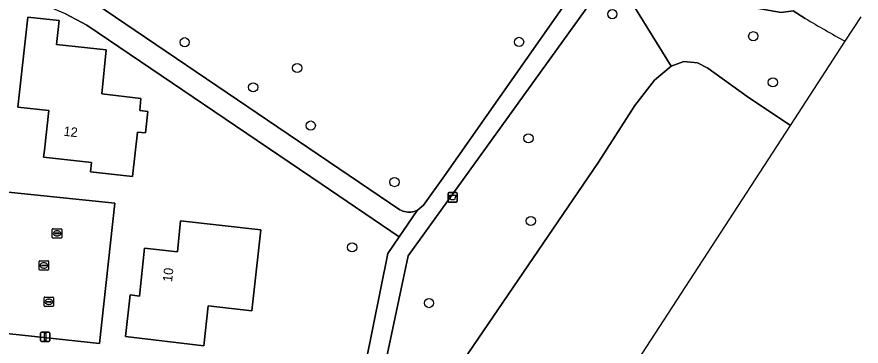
# Model space of a CAD drawing. Extents: x 161928 to 163071, y 386474 to 387428.
# Drawn here: x 162422.4 to 162512.1, y 386616.9 to 386651.9 of the extents above; entities that cross this region are included whole.
import ezdxf

# ---------------------------------------------------------------- set-up
doc = ezdxf.new("R2010")
doc.units = 0
for name, color, linetype in [('IMGEO_Afvalbak', 7, 'Continuous'), ('IMGEO_Boom', 7, 'Continuous'), ('IMGEO_Erf', 7, 'Continuous'), ('IMGEO_Groenvoorziening', 7, 'Continuous'), ('IMGEO_Kolk', 7, 'Continuous'), ('IMGEO_Lichtmast', 7, 'Continuous'), ('IMGEO_Meer_plas_ven_vijver', 7, 'Continuous'), ('IMGEO_Pand', 7, 'Continuous'), ('IMGEO_Pand_nummerreeks', 7, 'Continuous'), ('IMGEO_Rijbaan_lokaal_open', 7, 'Continuous'), ('IMGEO_Rioolput', 7, 'Continuous'), ('IMGEO_Voetpad_halfverhard', 7, 'Continuous'), ('IMGEO_Voetpad_open', 7, 'Continuous')]:
    doc.layers.add(name, color=color, linetype=linetype)

msp = doc.modelspace()

# ---------------------------------------------------------------- linework, layer by layer
at = {"layer": 'IMGEO_Afvalbak'}
for p, q in [((162468.22, 386632.306), (162468.22, 386633.106)), ((162468.22, 386633.106), (162468.22, 386632.306)), ((162468.32, 386633.206), (162469.11, 386633.206)), ((162469.11, 386633.206), (162468.32, 386633.206)), ((162469.21, 386633.106), (162469.21, 386632.306)), ((162469.21, 386632.306), (162469.21, 386633.106)), ((162469.11, 386632.206), (162468.32, 386632.206)), ((162468.32, 386632.206), (162469.11, 386632.206))]:
    msp.add_line(p, q, dxfattribs=at)
msp.add_lwpolyline([(162468.363, 386632.92), (162469.067, 386632.92), (162468.918, 386632.45), (162468.512, 386632.45), (162468.363, 386632.92)], dxfattribs=at)
for centre, start, end in [((162468.32, 386633.106), 90, 180), ((162468.32, 386633.106), 90, 180), ((162469.11, 386633.106), 0, 90), ((162469.11, 386633.106), 360, 90), ((162468.32, 386632.306), 180, 270), ((162468.32, 386632.306), 180, 270), ((162469.11, 386632.306), 270, 0), ((162469.11, 386632.306), 270, 0)]:
    msp.add_arc(centre, 0.1, start, end, dxfattribs=at)
at = {"layer": 'IMGEO_Boom'}
for centre in [(162485.683, 386652.188), (162500.662, 386649.842), (162440.231, 386649.202), (162475.774, 386649.237), (162452.191, 386646.458), (162447.512, 386644.407), (162502.751, 386644.934), (162453.631, 386640.337), (162476.768, 386638.978), (162462.536, 386634.326), (162477.027, 386630.191), (162458.028, 386627.386), (162466.196, 386621.456)]:
    msp.add_circle(centre, 0.489, dxfattribs=at)
at = {"layer": 'IMGEO_Erf'}
for points in [[(162454.731, 386634.129), (162429.842, 386651.007), (162427.559, 386652.217), (162425.176, 386653.219), (162422.714, 386654.003), (162420.192, 386654.565), (162418.483, 386654.813), (162405.257, 386656.292), (162404.515, 386649.308), (162403.939, 386643.891), (162402.493, 386630.278), (162416.503, 386628.855)], [(162415.579, 386623.904), (162401.954, 386625.399), (162400.548, 386612.657), (162395.336, 386564.99), (162414.895, 386562.738), (162421.638, 386561.962), (162444.564, 386594.917), (162445.356, 386594.4), (162447.893, 386598.102), (162459.435, 386614.943), (162461.829, 386626.715), (162463.03, 386628.501), (162454.731, 386634.129)], [(162420.711, 386632.302), (162420.785, 386633.326), (162432.793, 386632.1), (162431.191, 386617.163), (162419.313, 386618.428), (162419.342, 386619.587)]]:
    msp.add_lwpolyline(points, dxfattribs=at)
for points in [[(162422.482, 386642.308), (162423.277, 386649.318), (162423.568, 386651.883), (162426.903, 386651.52), (162426.624, 386648.954), (162431.897, 386648.381), (162431.422, 386643.704), (162435.586, 386643.231), (162435.464, 386641.939), (162436.32, 386641.836), (162436.084, 386639.557), (162435.227, 386639.637), (162434.673, 386634.909), (162430.22, 386635.411), (162430.319, 386636.393), (162425.232, 386636.966), (162425.319, 386637.74), (162425.792, 386641.935)], [(162439.453, 386626.908), (162439.792, 386630.221), (162448.336, 386629.248), (162447.381, 386620.627), (162442.745, 386621.147), (162442.266, 386616.916), (162433.928, 386617.89), (162434.425, 386622.336), (162435.429, 386622.204), (162435.974, 386627.293)]]:
    msp.add_lwpolyline(points, close=True, dxfattribs=at)
at = {"layer": 'IMGEO_Groenvoorziening'}
for points in [[(162430.677, 386653.35), (162463.112, 386631.382), (162463.267, 386631.302), (162463.428, 386631.236), (162463.595, 386631.185), (162463.765, 386631.15), (162463.938, 386631.129), (162464.112, 386631.124), (162464.286, 386631.134), (162464.458, 386631.16), (162464.627, 386631.202), (162464.792, 386631.258), (162464.925, 386631.316), (162465.604, 386631.858), (162467.845, 386635.008), (162488.421, 386664.371)], [(162422.397, 386543.77), (162427.166, 386551.666), (162433.134, 386560.84), (162440.537, 386571.577), (162443.391, 386575.338), (162463.65, 386605.442), (162468.197, 386612.928), (162484.213, 386636.459), (162488.061, 386642.46), (162490.173, 386645.183), (162491.955, 386646.67), (162486.524, 386655.466), (162484.527, 386655.077), (162463.996, 386626.469), (162461.367, 386614.091), (162441.634, 386585.218), (162440.702, 386585.864), (162418.182, 386553.338)], [(162506.186, 386651.728), (162504.888, 386652.554), (162503.64, 386652.359), (162500, 386653.02), (162486.524, 386655.466), (162491.955, 386646.67), (162493.287, 386647.171), (162494.722, 386647.011), (162495.834, 386646.435), (162500, 386643.42), (162504.627, 386640.362), (162510.432, 386649.303)]]:
    msp.add_lwpolyline(points, dxfattribs=at)
msp.add_arc((162647.941, 386895.038), 281.592, 239.77456, 240.76941, dxfattribs=at)
at = {"layer": 'IMGEO_Kolk'}
for p, q in [((162426.164, 386628.446), (162426.164, 386629.298)), ((162426.239, 386629.372), (162427.091, 386629.372)), ((162426.423, 386628.866), (162426.423, 386628.878)), ((162426.861, 386628.829), (162426.463, 386628.829)), ((162426.466, 386628.915), (162426.864, 386628.915)), ((162426.675, 386628.592), (162426.65, 386628.592)), ((162426.652, 386629.152), (162426.677, 386629.152)), ((162426.907, 386628.878), (162426.907, 386628.866)), ((162427.165, 386629.298), (162427.165, 386628.446)), ((162427.091, 386628.372), (162426.239, 386628.372)), ((162425.283, 386621.171), (162425.283, 386622.023)), ((162425.358, 386622.097), (162426.21, 386622.097)), ((162425.542, 386621.591), (162425.542, 386621.603)), ((162425.98, 386621.554), (162425.582, 386621.554)), ((162425.585, 386621.64), (162425.983, 386621.64)), ((162425.771, 386621.877), (162425.796, 386621.877)), ((162426.026, 386621.603), (162426.026, 386621.591)), ((162426.284, 386622.023), (162426.284, 386621.171)), ((162426.21, 386621.097), (162425.358, 386621.097)), ((162425.794, 386621.317), (162425.769, 386621.317))]:
    msp.add_line(p, q, dxfattribs=at)
for points in [[(162426.164, 386628.446), (162426.164, 386629.298)], [(162426.239, 386629.372), (162427.091, 386629.372)], [(162427.165, 386629.298), (162427.165, 386628.446)], [(162427.091, 386628.372), (162426.239, 386628.372)], [(162425.283, 386621.171), (162425.283, 386622.023)], [(162425.358, 386622.097), (162426.21, 386622.097)], [(162426.284, 386622.023), (162426.284, 386621.171)], [(162426.21, 386621.097), (162425.358, 386621.097)]]:
    msp.add_lwpolyline(points, dxfattribs=at)
for centre, radius, start, end in [((162426.241, 386629.296), 0.0765, 91.55205, 178.44795), ((162426.241, 386629.296), 0.0765, 91.55205, 178.44795), ((162426.463, 386628.875), 0.0403, 85.87752, 175.75265), ((162426.46, 386628.865), 0.0366, 178.93798, 274.71019), ((162426.864, 386628.872), 0.043, 264.86636, 352.45326), ((162426.868, 386628.877), 0.0386, 1.73085, 96.63898), ((162427.089, 386629.296), 0.0765, 1.55205, 88.44795), ((162427.089, 386629.296), 0.0765, 1.55205, 88.44795), ((162426.241, 386628.448), 0.0765, 181.55205, 268.44795), ((162426.241, 386628.448), 0.0765, 181.55205, 268.44795), ((162427.089, 386628.448), 0.0765, 271.55205, 358.44795), ((162427.089, 386628.448), 0.0765, 271.55205, 358.44795), ((162425.36, 386622.021), 0.0765, 91.55205, 178.44795), ((162425.36, 386622.021), 0.0765, 91.55205, 178.44795), ((162425.582, 386621.6), 0.0403, 85.87752, 175.75265), ((162425.579, 386621.59), 0.0366, 178.93798, 274.71019), ((162425.983, 386621.597), 0.043, 264.86636, 352.45326), ((162425.987, 386621.602), 0.0386, 1.73085, 96.63898), ((162426.208, 386622.021), 0.0765, 1.55205, 88.44795), ((162426.208, 386622.021), 0.0765, 1.55205, 88.44795), ((162425.36, 386621.173), 0.0765, 181.55205, 268.44795), ((162425.36, 386621.173), 0.0765, 181.55205, 268.44795), ((162426.208, 386621.173), 0.0765, 271.55205, 358.44795), ((162426.208, 386621.173), 0.0765, 271.55205, 358.44795)]:
    msp.add_arc(centre, radius, start, end, dxfattribs=at)
for centre, major_axis, ratio, start_param, end_param in [((162426.651, 386628.872), (-0.387, 0.002), 0.722429, 4.712389, 7.853982), ((162426.676, 386628.872), (-0.39, 0.002), 0.717154, 1.570796, 4.712389), ((162425.77, 386621.597), (-0.387, 0.002), 0.722429, 4.712389, 7.853982), ((162425.795, 386621.597), (-0.39, 0.002), 0.717154, 1.570796, 4.712389)]:
    msp.add_ellipse(centre, major_axis=major_axis, ratio=ratio, start_param=start_param, end_param=end_param, dxfattribs=at)
at = {"layer": 'IMGEO_Lichtmast'}
for p, q in [((162424.904, 386617.466), (162424.904, 386618.266)), ((162424.904, 386618.266), (162424.904, 386617.466)), ((162425.004, 386618.366), (162425.794, 386618.366)), ((162425.794, 386618.366), (162425.004, 386618.366)), ((162425.894, 386618.266), (162425.894, 386617.466)), ((162425.894, 386617.466), (162425.894, 386618.266)), ((162425.794, 386617.366), (162425.004, 386617.366)), ((162425.004, 386617.366), (162425.794, 386617.366))]:
    msp.add_line(p, q, dxfattribs=at)
msp.add_lwpolyline([(162425.324, 386618.241), (162425.474, 386618.241), (162425.474, 386617.491), (162425.324, 386617.491), (162425.324, 386618.241)], dxfattribs=at)
for centre, start, end in [((162425.004, 386618.266), 90, 180), ((162425.004, 386618.266), 90, 180), ((162425.794, 386618.266), 0, 90), ((162425.794, 386618.266), 360, 90), ((162425.004, 386617.466), 180, 270), ((162425.004, 386617.466), 180, 270), ((162425.794, 386617.466), 270, 0), ((162425.794, 386617.466), 270, 0)]:
    msp.add_arc(centre, 0.1, start, end, dxfattribs=at)
at = {"layer": 'IMGEO_Meer_plas_ven_vijver'}
msp.add_lwpolyline([(162413.433, 386500.536), (162486.069, 386611.772), (162504.627, 386640.362), (162500, 386643.42), (162495.834, 386646.435), (162494.722, 386647.011), (162493.287, 386647.171), (162491.955, 386646.67), (162490.173, 386645.183), (162488.061, 386642.46), (162484.213, 386636.459), (162468.197, 386612.928), (162463.65, 386605.442), (162443.391, 386575.338), (162440.537, 386571.577), (162433.134, 386560.84), (162427.166, 386551.666), (162422.397, 386543.77)], dxfattribs=at)
at = {"layer": 'IMGEO_Pand'}
for points in [[(162436.32, 386641.836), (162435.464, 386641.939), (162435.586, 386643.231), (162431.422, 386643.704), (162431.897, 386648.381), (162426.624, 386648.954), (162426.903, 386651.52), (162423.568, 386651.883), (162423.277, 386649.318), (162422.482, 386642.308), (162425.792, 386641.935), (162425.319, 386637.74), (162425.232, 386636.966), (162430.319, 386636.393), (162430.22, 386635.411), (162434.673, 386634.909), (162435.227, 386639.637), (162436.084, 386639.557)], [(162435.429, 386622.204), (162434.425, 386622.336), (162433.928, 386617.89), (162442.266, 386616.916), (162442.745, 386621.147), (162447.381, 386620.627), (162448.336, 386629.248), (162439.792, 386630.221), (162439.453, 386626.908), (162435.974, 386627.293)]]:
    msp.add_lwpolyline(points, close=True, dxfattribs=at)
at = {"layer": 'IMGEO_Rijbaan_lokaal_open'}
msp.add_lwpolyline([(162419.342, 386619.587), (162419.313, 386618.428), (162431.191, 386617.163), (162432.793, 386632.1), (162420.785, 386633.326), (162420.711, 386632.302)], dxfattribs=at)
at = {"layer": 'IMGEO_Rioolput'}
for p, q in [((162424.763, 386625.032), (162424.763, 386625.884)), ((162424.838, 386625.958), (162425.69, 386625.958)), ((162425.764, 386625.884), (162425.764, 386625.032)), ((162425.69, 386624.958), (162424.838, 386624.958)), ((162425.022, 386625.452), (162425.022, 386625.464)), ((162425.46, 386625.415), (162425.062, 386625.415)), ((162425.065, 386625.501), (162425.463, 386625.501)), ((162425.274, 386625.178), (162425.249, 386625.178)), ((162425.251, 386625.738), (162425.276, 386625.738)), ((162425.506, 386625.464), (162425.506, 386625.452))]:
    msp.add_line(p, q, dxfattribs=at)
for points in [[(162424.763, 386625.032), (162424.763, 386625.884)], [(162424.838, 386625.958), (162425.69, 386625.958)], [(162425.764, 386625.884), (162425.764, 386625.032)], [(162425.69, 386624.958), (162424.838, 386624.958)]]:
    msp.add_lwpolyline(points, dxfattribs=at)
for centre, radius, start, end in [((162424.84, 386625.882), 0.0765, 91.55205, 178.44795), ((162424.84, 386625.882), 0.0765, 91.55205, 178.44795), ((162425.688, 386625.882), 0.0765, 1.55205, 88.44795), ((162425.688, 386625.882), 0.0765, 1.55205, 88.44795), ((162424.84, 386625.034), 0.0765, 181.55205, 268.44795), ((162424.84, 386625.034), 0.0765, 181.55205, 268.44795), ((162425.062, 386625.461), 0.0403, 85.87752, 175.75265), ((162425.059, 386625.451), 0.0366, 178.93798, 274.71019), ((162425.463, 386625.458), 0.043, 264.86636, 352.45326), ((162425.467, 386625.463), 0.0386, 1.73085, 96.63898), ((162425.688, 386625.034), 0.0765, 271.55205, 358.44795), ((162425.688, 386625.034), 0.0765, 271.55205, 358.44795)]:
    msp.add_arc(centre, radius, start, end, dxfattribs=at)
for centre, major_axis, ratio, start_param, end_param in [((162425.25, 386625.458), (-0.387, 0.002), 0.722429, 4.712389, 7.853982), ((162425.275, 386625.458), (-0.39, 0.002), 0.717154, 1.570796, 4.712389)]:
    msp.add_ellipse(centre, major_axis=major_axis, ratio=ratio, start_param=start_param, end_param=end_param, dxfattribs=at)
at = {"layer": 'IMGEO_Voetpad_halfverhard'}
for points in [[(162499.594, 386656.083), (162499.263, 386656.313), (162499.135, 386656.201), (162498.803, 386656.095), (162497.85, 386655.862), (162487.291, 386658.568), (162490.455, 386662.814), (162488.421, 386664.371), (162467.845, 386635.008), (162465.604, 386631.858), (162464.925, 386631.316), (162463.03, 386628.501), (162461.829, 386626.715), (162459.435, 386614.943), (162447.893, 386598.102), (162445.356, 386594.4), (162444.564, 386594.917), (162421.638, 386561.962), (162417.322, 386555.758)], [(162463.996, 386626.469), (162484.527, 386655.077), (162486.524, 386655.466), (162500, 386653.02), (162503.64, 386652.359), (162504.888, 386652.554)], [(162400.359, 386548.883), (162393.659, 386549.647), (162393.322, 386546.486), (162398.032, 386546.045), (162400.592, 386545.903), (162403.155, 386545.99), (162405.699, 386546.306), (162406.824, 386546.52), (162408.487, 386546.912), (162410.108, 386547.45), (162411.674, 386548.131), (162413.174, 386548.95), (162414.594, 386549.899), (162415.924, 386550.971), (162417.153, 386552.158), (162418.182, 386553.338), (162440.702, 386585.864), (162441.634, 386585.218), (162461.367, 386614.091), (162463.996, 386626.469)]]:
    msp.add_lwpolyline(points, dxfattribs=at)
at = {"layer": 'IMGEO_Voetpad_open'}
for points in [[(162427.559, 386652.217), (162429.842, 386651.007), (162454.731, 386634.129), (162463.03, 386628.501), (162464.925, 386631.316), (162464.792, 386631.258), (162464.627, 386631.202), (162464.458, 386631.16), (162464.286, 386631.134), (162464.112, 386631.124), (162463.938, 386631.129), (162463.765, 386631.15), (162463.595, 386631.185), (162463.428, 386631.236), (162463.267, 386631.302), (162463.112, 386631.382), (162430.677, 386653.35)], [(162504.888, 386652.554), (162506.186, 386651.728)], [(162510.432, 386649.303), (162512.127, 386651.916)]]:
    msp.add_lwpolyline(points, dxfattribs=at)
msp.add_arc((162647.941, 386895.038), 281.592, 239.77456, 240.76941, dxfattribs=at)

# ---------------------------------------------------------------- texts
at = {"layer": 'IMGEO_Pand_nummerreeks'}
for s, rotation, p in [('12', 353.57141, (162427.324, 386639.266)), ('10', 83.88728, (162438.885, 386623.672))]:
    msp.add_text(s, height=1, rotation=rotation, dxfattribs=at).set_placement(p)

doc.saveas('drawing.dxf')
